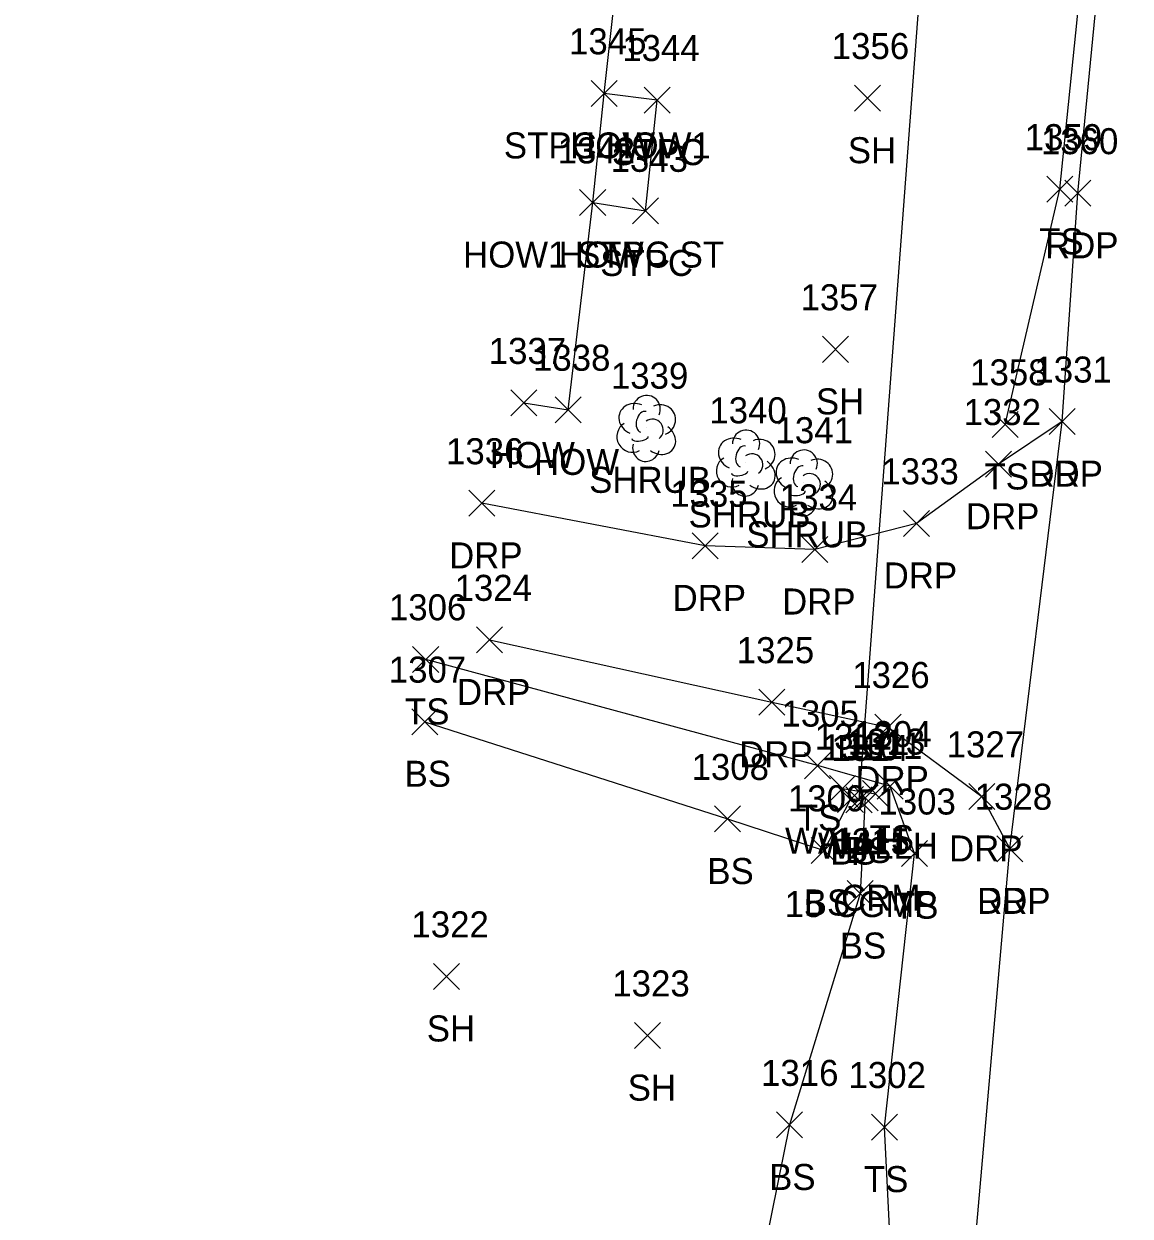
# Model space of a CAD drawing. Extents: x 1653908 to 1654393, y 539913 to 544256.
# Drawn here: x 1653956 to 1654041, y 541381.8 to 541473.4 of the extents above; entities that cross this region are included whole.
import ezdxf

# ---------------------------------------------------------------- set-up
doc = ezdxf.new("R2010")
doc.units = 0
for name, color, linetype in [('D_A', 7, 'Continuous'), ('D_C', 7, 'Continuous'), ('D_I', 7, 'Continuous'), ('D_TIC', 7, 'Continuous'), ('DCP', 7, 'Continuous'), ('DHW', 7, 'Continuous'), ('L_A', 7, 'Continuous'), ('L_I', 7, 'Continuous'), ('L_TIC', 7, 'Continuous'), ('LBC', 7, 'Continuous'), ('LBF', 7, 'Continuous'), ('LELB', 7, 'Continuous'), ('LSH', 7, 'Continuous'), ('P_A', 7, 'Continuous'), ('P_I', 7, 'Continuous'), ('P_TIC', 7, 'Continuous'), ('PET', 7, 'Continuous'), ('R_A', 7, 'Continuous'), ('R_I', 7, 'Continuous'), ('R_TIC', 7, 'Continuous'), ('RDP', 7, 'Continuous')]:
    doc.layers.add(name, color=color, linetype=linetype)

msp = doc.modelspace()

# ---------------------------------------------------------------- linework, layer by layer
at = {"layer": 'D_TIC'}
for points in [[(1654017.935, 541413.625), (1654019.935, 541415.625)], [(1654019.935, 541413.625), (1654017.935, 541415.625)], [(1654020.464, 541413.236), (1654022.464, 541415.236)], [(1654022.464, 541413.236), (1654020.464, 541415.236)], [(1654019.208, 541412.754), (1654021.208, 541414.754)], [(1654021.208, 541412.754), (1654019.208, 541414.754)]]:
    msp.add_lwpolyline(points, dxfattribs=at)
at = {"layer": 'DCP'}
msp.add_lwpolyline([(1654020.208, 541413.754), (1654026.48, 541496.947)], dxfattribs=at)
at = {"layer": 'DHW'}
msp.add_lwpolyline([(1654018.935, 541414.625), (1654021.464, 541414.236)], dxfattribs=at)
at = {"layer": 'L_TIC'}
for points in [[(1653999.621, 541467.041), (1654001.621, 541469.041)], [(1654001.621, 541467.041), (1653999.621, 541469.041)], [(1653999.621, 541467.041), (1654001.621, 541469.041)], [(1654001.621, 541467.041), (1653999.621, 541469.041)], [(1654003.712, 541466.526), (1654005.712, 541468.526)], [(1654005.712, 541466.526), (1654003.712, 541468.526)], [(1654019.861, 541466.675), (1654021.861, 541468.675)], [(1654021.861, 541466.675), (1654019.861, 541468.675)], [(1654034.64, 541459.677), (1654036.64, 541461.677)], [(1654036.64, 541459.677), (1654034.64, 541461.677)], [(1653998.746, 541458.658), (1654000.746, 541460.658)], [(1654000.746, 541458.658), (1653998.746, 541460.658)], [(1653998.746, 541458.658), (1654000.746, 541460.658)], [(1654000.746, 541458.658), (1653998.746, 541460.658)], [(1654002.813, 541458.013), (1654004.813, 541460.013)], [(1654004.813, 541458.013), (1654002.813, 541460.013)], [(1654017.408, 541447.376), (1654019.408, 541449.376)], [(1654019.408, 541447.376), (1654017.408, 541449.376)], [(1653993.454, 541443.255), (1653995.454, 541445.255)], [(1653995.454, 541443.255), (1653993.454, 541445.255)], [(1653996.854, 541442.729), (1653998.854, 541444.729)], [(1653998.854, 541442.729), (1653996.854, 541444.729)], [(1654030.439, 541441.607), (1654032.439, 541443.607)], [(1654032.439, 541441.607), (1654030.439, 541443.607)], [(1653985.915, 541423.555), (1653987.915, 541425.555)], [(1653987.915, 541423.555), (1653985.915, 541425.555)], [(1653985.851, 541418.767), (1653987.851, 541420.767)], [(1653987.851, 541418.767), (1653985.851, 541420.767)], [(1654016.025, 541415.388), (1654018.025, 541417.388)], [(1654018.025, 541415.388), (1654016.025, 541417.388)], [(1654021.609, 541413.814), (1654023.609, 541415.814)], [(1654023.609, 541413.814), (1654021.609, 541415.814)], [(1654018.555, 541412.789), (1654020.555, 541414.789)], [(1654020.555, 541412.789), (1654018.555, 541414.789)], [(1654019.683, 541412.911), (1654021.683, 541414.911)], [(1654021.683, 541412.911), (1654019.683, 541414.911)], [(1654009.112, 541411.292), (1654011.112, 541413.292)], [(1654011.112, 541411.292), (1654009.112, 541413.292)], [(1654016.524, 541408.875), (1654018.524, 541410.875)], [(1654018.524, 541408.875), (1654016.524, 541410.875)], [(1654023.472, 541408.633), (1654025.472, 541410.633)], [(1654025.472, 541408.633), (1654023.472, 541410.633)], [(1654019.292, 541405.568), (1654021.292, 541407.568)], [(1654021.292, 541405.568), (1654019.292, 541407.568)], [(1653987.511, 541399.196), (1653989.511, 541401.196)], [(1653989.511, 541399.196), (1653987.511, 541401.196)], [(1654002.949, 541394.654), (1654004.949, 541396.654)], [(1654004.949, 541394.654), (1654002.949, 541396.654)], [(1654013.863, 541387.785), (1654015.863, 541389.785)], [(1654015.863, 541387.785), (1654013.863, 541389.785)], [(1654021.174, 541387.621), (1654023.174, 541389.621)], [(1654023.174, 541387.621), (1654021.174, 541389.621)]]:
    msp.add_lwpolyline(points, dxfattribs=at)
at = {"layer": 'LBC'}
msp.add_lwpolyline([(1653994.454, 541444.255), (1653997.854, 541443.729), (1653999.746, 541459.658), (1654000.621, 541468.041), (1654002.431, 541484.206), (1653956.042, 541489.339)], dxfattribs=at)
at = {"layer": 'LBF'}
msp.add_lwpolyline([(1653999.746, 541459.658), (1654003.813, 541459.013), (1654004.712, 541467.526), (1654000.621, 541468.041)], dxfattribs=at)
at = {"layer": 'LELB'}
for points in [[(1654031.439, 541442.607), (1654035.64, 541460.677), (1654038.793, 541491.482)], [(1654019.186, 541334.474), (1654023.261, 541366.471), (1654022.174, 541388.621), (1654024.472, 541409.633), (1654022.609, 541414.814), (1654017.025, 541416.388), (1653986.915, 541424.555)], [(1653986.851, 541419.767), (1654010.112, 541412.292), (1654017.524, 541409.875), (1654019.555, 541413.789), (1654020.683, 541413.911), (1654020.292, 541406.568), (1654014.863, 541388.785), (1654011.21, 541370.687), (1653984.158, 541373.791)]]:
    msp.add_lwpolyline(points, dxfattribs=at)
at = {"layer": 'LSH'}
for p, q in [((1654003.845, 541442.349), (1654003.845, 541442.349)), ((1654003.845, 541442.349), (1654003.845, 541442.349)), ((1654011.487, 541439.689), (1654011.487, 541439.689)), ((1654011.487, 541439.689), (1654011.487, 541439.689)), ((1654015.916, 541438.162), (1654015.916, 541438.162)), ((1654015.916, 541438.162), (1654015.916, 541438.162))]:
    msp.add_line(p, q, dxfattribs=at)
for centre in [(1654003.891, 541443.783), (1654011.534, 541441.123), (1654015.963, 541439.596)]:
    msp.add_arc(centre, 1.047, 335.52715, 180.95627, dxfattribs=at)
for centre, major_axis, ratio, start_param, end_param in [((1654003.053, 541443.016), (1.21, -0.512), 0.895232, 1.570796, 4.712389), ((1654003.636, 541442.807), (-0.208, -0.792), 0.645439, 3.141593, 6.283185), ((1654004.886, 541442.933), (-1.141, -0.483), 0.949671, 1.570796, 4.712389), ((1654002.761, 541441.641), (0.584, -1.042), 0.959034, 3.141593, 6.283185), ((1654004.345, 541442.183), (-0.5, 0.667), 0.989748, 3.141593, 6.283185), ((1654004.845, 541441.516), (-1.09, 0.792), 0.841452, 1.570796, 4.712389), ((1654010.695, 541440.356), (1.21, -0.512), 0.895232, 1.570796, 4.712389), ((1654003.845, 541440.849), (0.265, 1.061), 0.942809, 1.570796, 4.712389), ((1654003.386, 541441.599), (-0.625, -0.083), 0.423636, 0, 3.141593), ((1654011.279, 541440.148), (-0.208, -0.792), 0.645439, 3.141593, 6.283185), ((1654012.529, 541440.273), (-1.141, -0.483), 0.949671, 1.570796, 4.712389), ((1654010.404, 541438.981), (0.584, -1.042), 0.959034, 3.141593, 6.283185), ((1654011.987, 541439.523), (-0.5, 0.667), 0.989748, 3.141593, 6.283185), ((1654015.125, 541438.829), (1.21, -0.512), 0.895232, 1.570796, 4.712389), ((1654016.958, 541438.746), (-1.141, -0.483), 0.949671, 1.570796, 4.712389), ((1654011.029, 541438.939), (-0.625, -0.083), 0.423636, 0, 3.141593), ((1654012.487, 541438.856), (-1.09, 0.792), 0.841452, 1.570796, 4.712389), ((1654015.708, 541438.621), (-0.208, -0.792), 0.645439, 3.141593, 6.283185), ((1654011.487, 541438.189), (0.265, 1.061), 0.942809, 1.570796, 4.712389), ((1654014.833, 541437.454), (0.584, -1.042), 0.959034, 3.141593, 6.283185), ((1654016.416, 541437.996), (-0.5, 0.667), 0.989748, 3.141593, 6.283185), ((1654016.916, 541437.329), (-1.09, 0.792), 0.841452, 1.570796, 4.712389), ((1654015.458, 541437.412), (-0.625, -0.083), 0.423636, 0, 3.141593), ((1654015.917, 541436.662), (0.265, 1.061), 0.942809, 1.570796, 4.712389)]:
    msp.add_ellipse(centre, major_axis=major_axis, ratio=ratio, start_param=start_param, end_param=end_param, dxfattribs=at)
at = {"layer": 'P_TIC'}
for points in [[(1654036.011, 541459.368), (1654038.011, 541461.368)], [(1654038.011, 541459.368), (1654036.011, 541461.368)], [(1654034.81, 541441.822), (1654036.81, 541443.822)], [(1654036.81, 541441.822), (1654034.81, 541443.822)], [(1654030.788, 541409.001), (1654032.788, 541411.001)], [(1654032.788, 541409.001), (1654030.788, 541411.001)]]:
    msp.add_lwpolyline(points, dxfattribs=at)
at = {"layer": 'PET'}
msp.add_lwpolyline([(1654002.711, 541022.85), (1654002.8, 541044.575), (1654003.387, 541071.89), (1654004.237, 541078.688), (1654006.743, 541130.143), (1654008.352, 541153.982), (1654010.069, 541183.44), (1654012.885, 541209.942), (1654016.448, 541249.52), (1654022.907, 541308.117), (1654024.639, 541328.517), (1654031.788, 541410.001), (1654035.81, 541442.822), (1654037.011, 541460.368), (1654040.035, 541491.488), (1654045.583, 541525.885), (1654049.594, 541568.112), (1654053.328, 541590.161), (1654054.271, 541598.349), (1654062.589, 541587.523), (1654071.875, 541577.056), (1654070.193, 541559.907), (1654067.659, 541531.505), (1654064.32, 541497.282)], dxfattribs=at)
at = {"layer": 'R_TIC'}
for points in [[(1654034.81, 541441.822), (1654036.81, 541443.822)], [(1654036.81, 541441.822), (1654034.81, 541443.822)], [(1654029.932, 541438.556), (1654031.932, 541440.556)], [(1654031.932, 541438.556), (1654029.932, 541440.556)], [(1653990.225, 541435.545), (1653992.225, 541437.545)], [(1653992.225, 541435.545), (1653990.225, 541437.545)], [(1654023.616, 541434.002), (1654025.616, 541436.002)], [(1654025.616, 541434.002), (1654023.616, 541436.002)], [(1654007.395, 541432.279), (1654009.395, 541434.279)], [(1654009.395, 541432.279), (1654007.395, 541434.279)], [(1654015.809, 541432.001), (1654017.809, 541434.001)], [(1654017.809, 541432.001), (1654015.809, 541434.001)], [(1653990.827, 541425.05), (1653992.827, 541427.05)], [(1653992.827, 541425.05), (1653990.827, 541427.05)], [(1654012.507, 541420.262), (1654014.507, 541422.262)], [(1654014.507, 541420.262), (1654012.507, 541422.262)], [(1654021.437, 541418.355), (1654023.437, 541420.355)], [(1654023.437, 541418.355), (1654021.437, 541420.355)], [(1654028.635, 541413.026), (1654030.635, 541415.026)], [(1654030.635, 541413.026), (1654028.635, 541415.026)], [(1654030.788, 541409.001), (1654032.788, 541411.001)], [(1654032.788, 541409.001), (1654030.788, 541411.001)]]:
    msp.add_lwpolyline(points, dxfattribs=at)
at = {"layer": 'RDP'}
for points in [[(1654035.81, 541442.822), (1654030.932, 541439.556), (1654024.616, 541435.002), (1654016.809, 541433.001), (1654008.395, 541433.279), (1653991.225, 541436.545)], [(1653991.827, 541426.05), (1654013.507, 541421.262), (1654022.437, 541419.355), (1654029.635, 541414.026), (1654031.788, 541410.001)]]:
    msp.add_lwpolyline(points, dxfattribs=at)

# ---------------------------------------------------------------- texts
at = {"layer": 'D_A'}
for s, p in [('WALLH', (1654014.525, 541409.625)), ('WALLH', (1654017.055, 541409.236)), ('P', (1654019.586, 541408.754))]:
    msp.add_text(s, height=2, dxfattribs=at).set_placement(p)
at = {"layer": 'D_C'}
for s, p in [('CRM', (1654018.834, 541405.236)), ('15 CGMP', (1654014.5, 541404.754))]:
    msp.add_text(s, height=2, dxfattribs=at).set_placement(p)
at = {"layer": 'D_I'}
for s, p in [('1312', (1654016.809, 541417.625)), ('1313', (1654019.338, 541417.236)), ('1314', (1654018.083, 541416.754))]:
    msp.add_text(s, height=2, dxfattribs=at).set_placement(p)
at = {"layer": 'L_A'}
for s, p in [('STPC HOW1', (1653992.92, 541463.041)), ('HOW', (1653998.007, 541463.041)), ('SH', (1654019.349, 541462.675)), ('STPC', (1654001.224, 541462.526)), ('TS', (1654034.05, 541455.677)), ('HOW1 STPC ST', (1653989.786, 541454.658)), ('HOW', (1653997.132, 541454.658)), ('STPC', (1654000.324, 541454.013)), ('SH', (1654016.896, 541443.376)), ('HOW', (1653991.84, 541439.255)), ('HOW', (1653995.24, 541438.729)), ('SHRUB', (1653999.474, 541437.349)), ('TS', (1654029.848, 541437.607)), ('SHRUB', (1654007.117, 541434.689)), ('SHRUB', (1654011.546, 541433.162)), ('TS', (1653985.325, 541419.555)), ('BS', (1653985.292, 541414.767)), ('TS', (1654015.434, 541411.388)), ('TS', (1654021.019, 541409.814)), ('BS', (1654017.996, 541408.789)), ('BS', (1654019.124, 541408.911)), ('BS', (1654008.553, 541407.292)), ('BS', (1654015.965, 541404.875)), ('TS', (1654022.881, 541404.633)), ('BS', (1654018.733, 541401.568)), ('SH', (1653986.999, 541395.196)), ('SH', (1654002.437, 541390.654)), ('BS', (1654013.304, 541383.785)), ('TS', (1654020.583, 541383.621))]:
    msp.add_text(s, height=2, dxfattribs=at).set_placement(p)
at = {"layer": 'L_I'}
for s, p in [('1345', (1653997.928, 541471.041)), ('1345', (1653997.928, 541471.041)), ('1344', (1654002.019, 541470.526)), ('1356', (1654018.113, 541470.675)), ('1359', (1654032.94, 541463.677)), ('1342', (1653997.053, 541462.658)), ('1342', (1653997.053, 541462.658)), ('1343', (1654001.12, 541462.013)), ('1357', (1654015.715, 541451.376)), ('1337', (1653991.761, 541447.255)), ('1338', (1653995.161, 541446.729)), ('1339', (1654001.144, 541445.349)), ('1358', (1654028.746, 541445.607)), ('1340', (1654008.708, 541442.689)), ('1341', (1654013.791, 541441.162)), ('1306', (1653984.089, 541427.555)), ('1307', (1653984.08, 541422.767)), ('1305', (1654014.253, 541419.388)), ('1304', (1654019.838, 541417.814)), ('1310', (1654017.342, 541416.789)), ('1311', (1654019.124, 541416.911)), ('1308', (1654007.341, 541415.292)), ('1309', (1654014.744, 541412.875)), ('1303', (1654021.7, 541412.633)), ('1315', (1654018.167, 541409.568)), ('1322', (1653985.818, 541403.196)), ('1323', (1654001.256, 541398.654)), ('1316', (1654012.682, 541391.785)), ('1302', (1654019.402, 541391.621))]:
    msp.add_text(s, height=2, dxfattribs=at).set_placement(p)
at = {"layer": 'P_A'}
for p in [(1654034.499, 541455.368), (1654033.299, 541437.822), (1654029.276, 541405.001)]:
    msp.add_text('RDP', height=2, dxfattribs=at).set_placement(p)
at = {"layer": 'P_I'}
for s, p in [('1360', (1654034.184, 541463.368)), ('1331', (1654033.685, 541445.822)), ('1328', (1654029.096, 541413.001))]:
    msp.add_text(s, height=2, dxfattribs=at).set_placement(p)
at = {"layer": 'R_A'}
for p in [(1654033.299, 541437.822), (1654028.42, 541434.556), (1653988.713, 541431.545), (1654022.104, 541430.002), (1654005.883, 541428.279), (1654014.298, 541428.001), (1653989.315, 541421.05), (1654010.995, 541416.262), (1654019.925, 541414.355), (1654027.124, 541409.026), (1654029.276, 541405.001)]:
    msp.add_text('DRP', height=2, dxfattribs=at).set_placement(p)
at = {"layer": 'R_I'}
for s, p in [('1331', (1654033.685, 541445.822)), ('1332', (1654028.239, 541442.556)), ('1336', (1653988.477, 541439.545)), ('1333', (1654021.923, 541438.002)), ('1335', (1654005.702, 541436.279)), ('1334', (1654014.117, 541436.001)), ('1324', (1653989.135, 541429.05)), ('1325', (1654010.814, 541424.262)), ('1326', (1654019.69, 541422.355)), ('1327', (1654026.943, 541417.026)), ('1328', (1654029.096, 541413.001))]:
    msp.add_text(s, height=2, dxfattribs=at).set_placement(p)

doc.saveas('drawing.dxf')
